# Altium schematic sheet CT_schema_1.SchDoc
size 554 x 508 mm
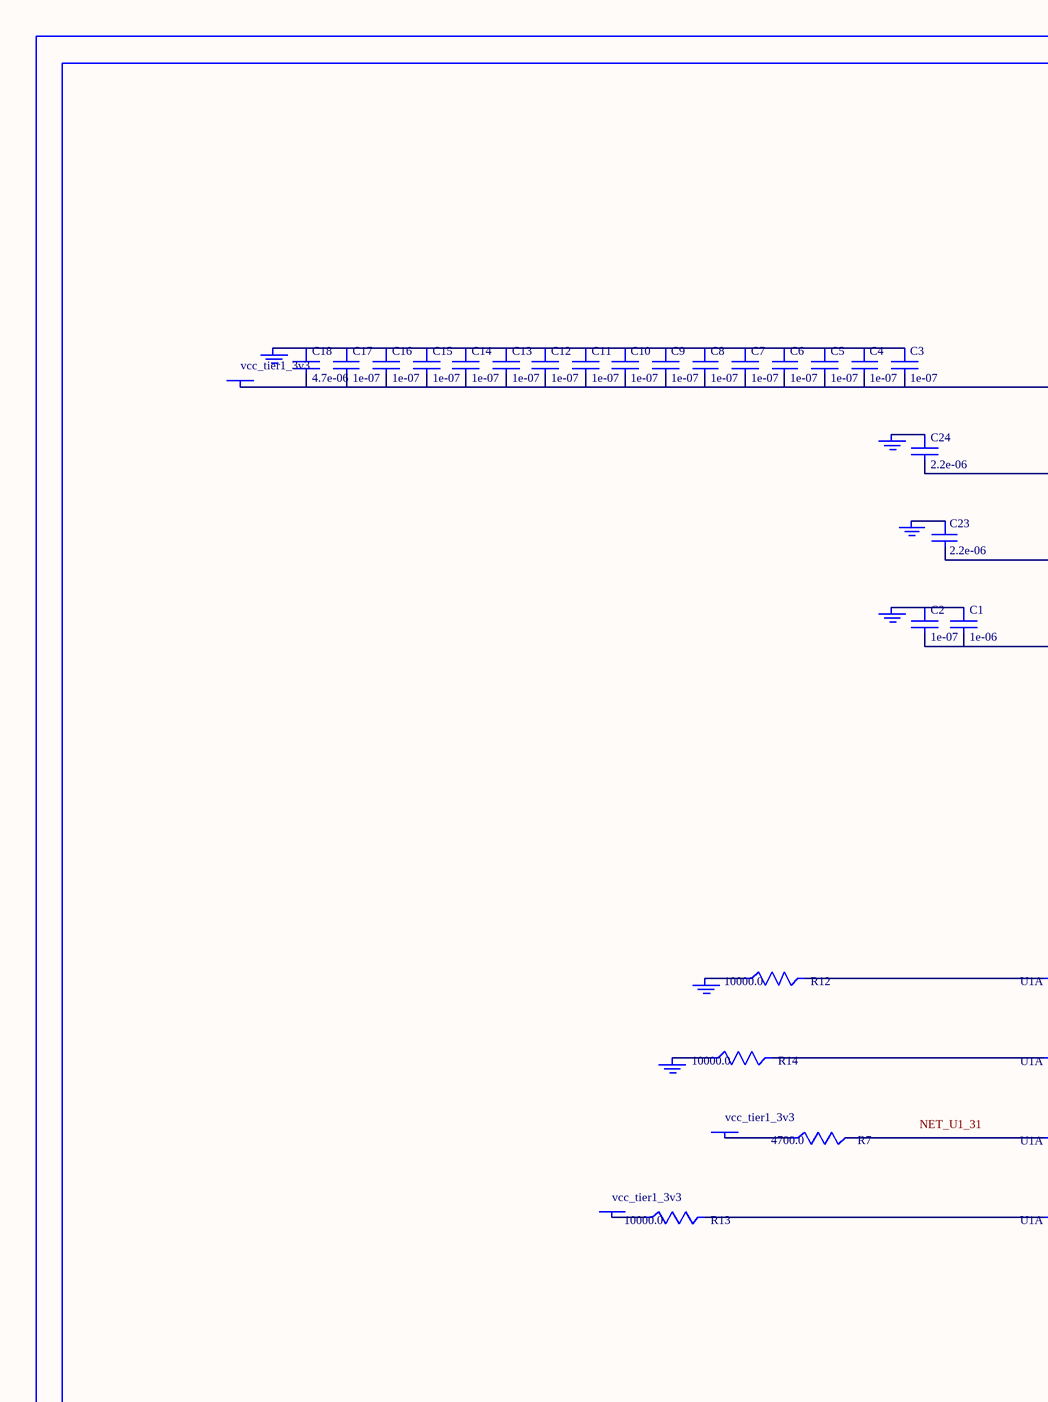
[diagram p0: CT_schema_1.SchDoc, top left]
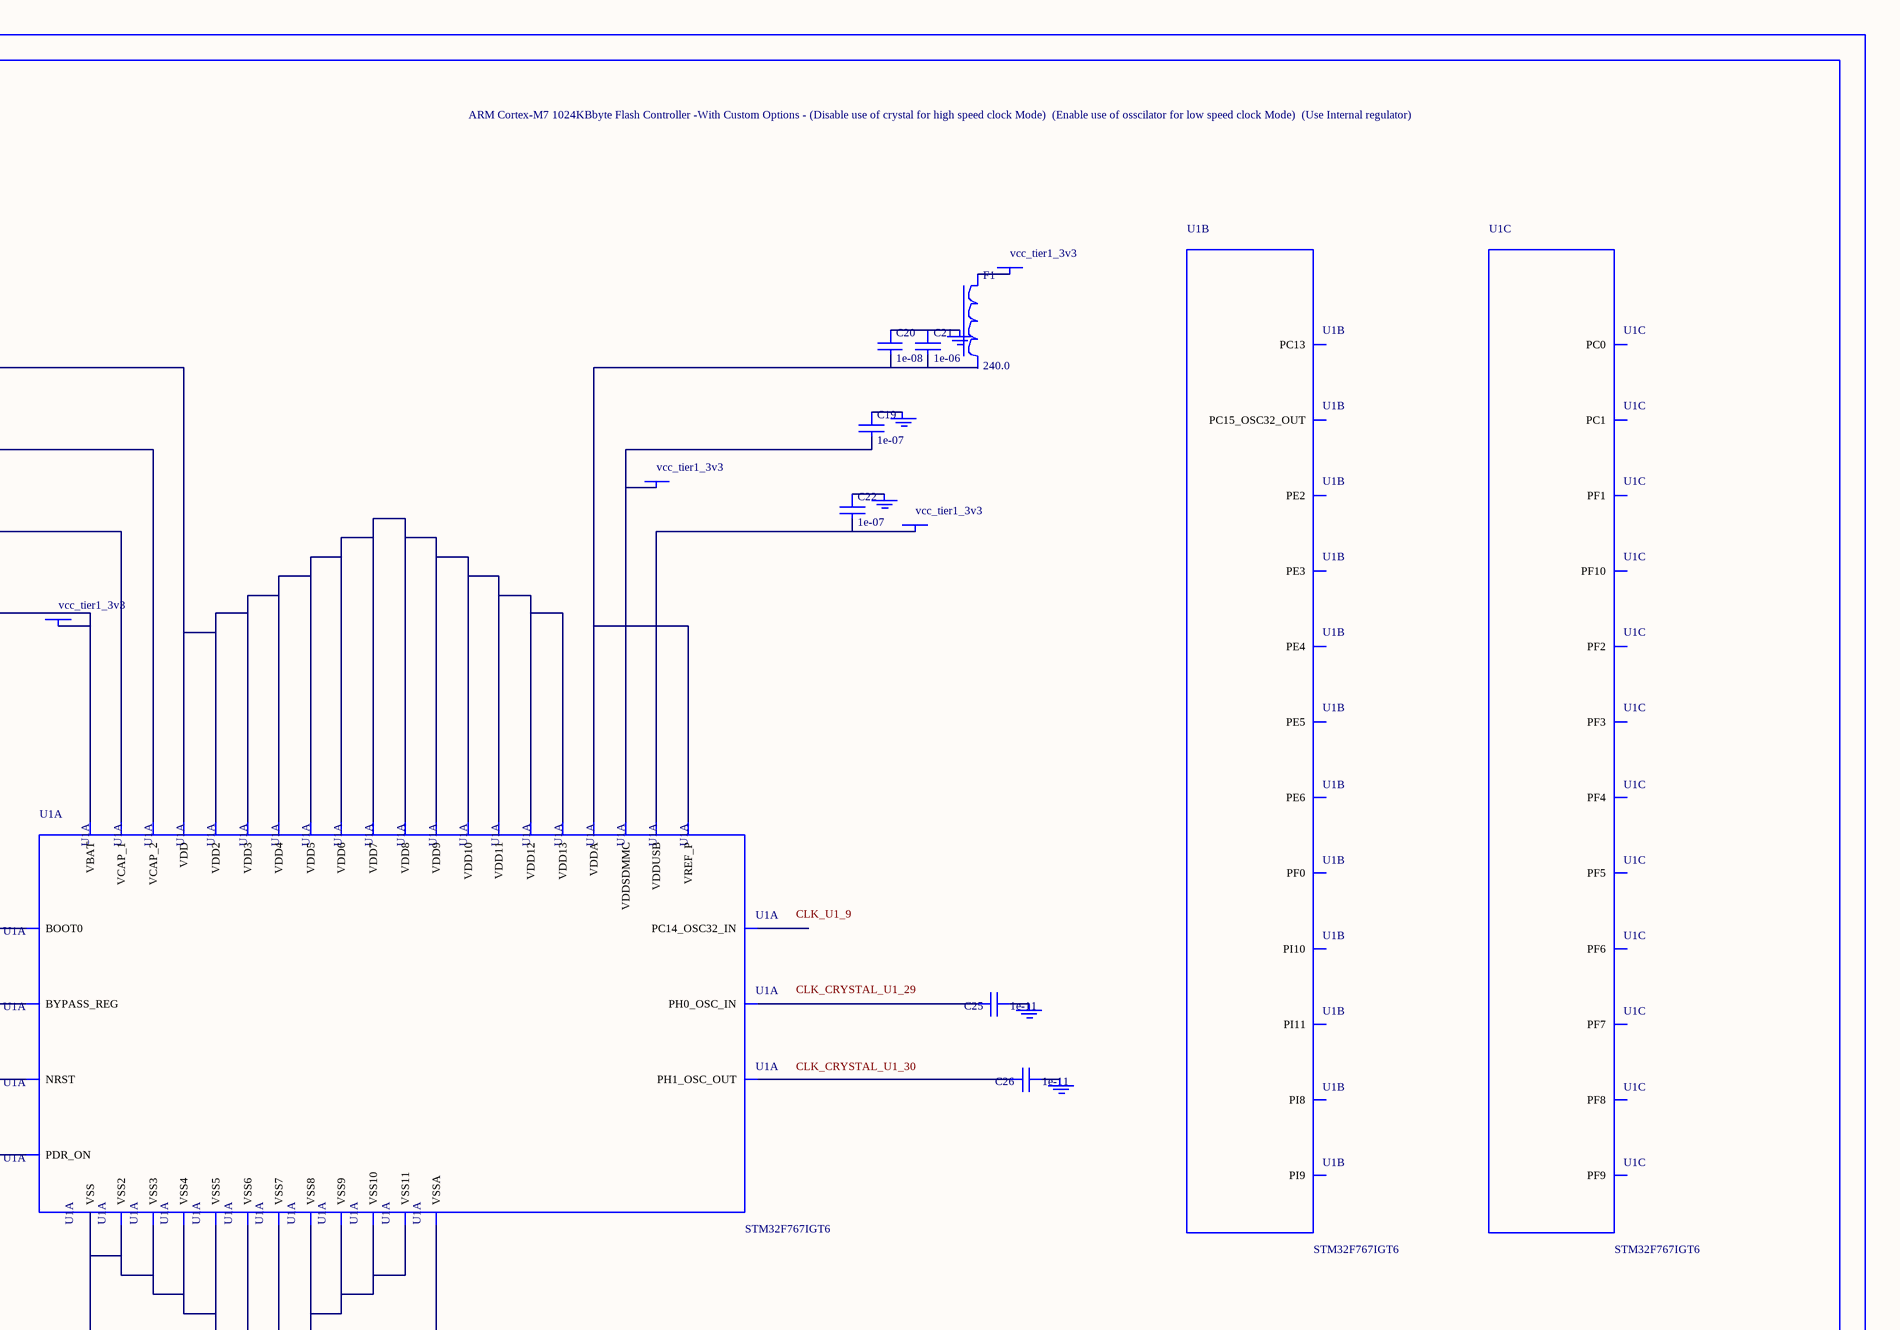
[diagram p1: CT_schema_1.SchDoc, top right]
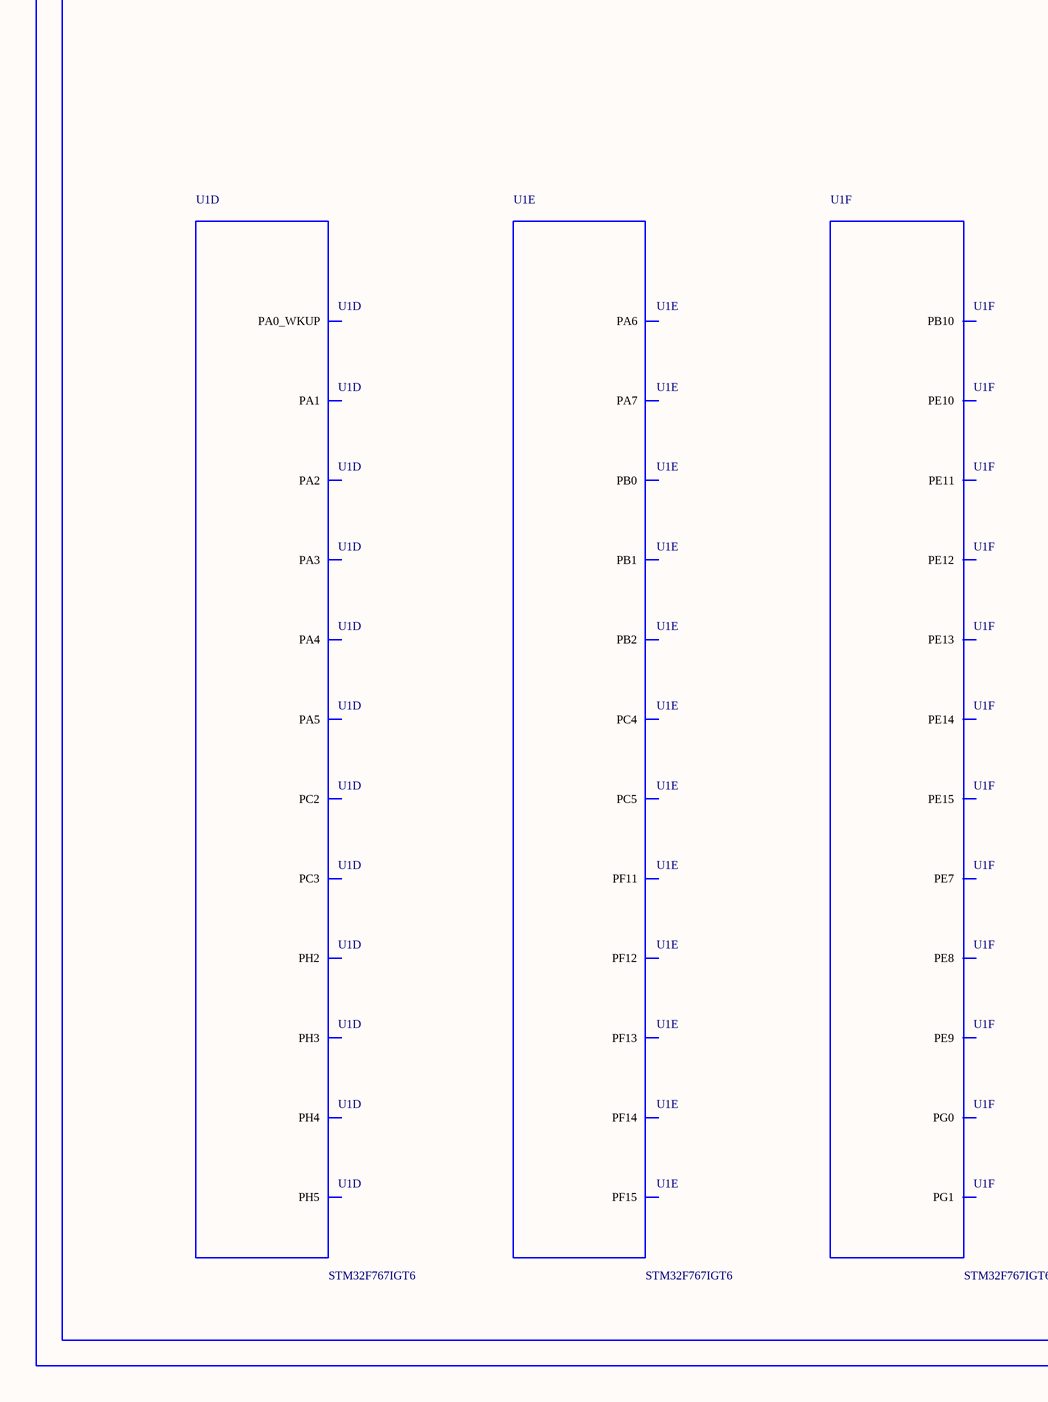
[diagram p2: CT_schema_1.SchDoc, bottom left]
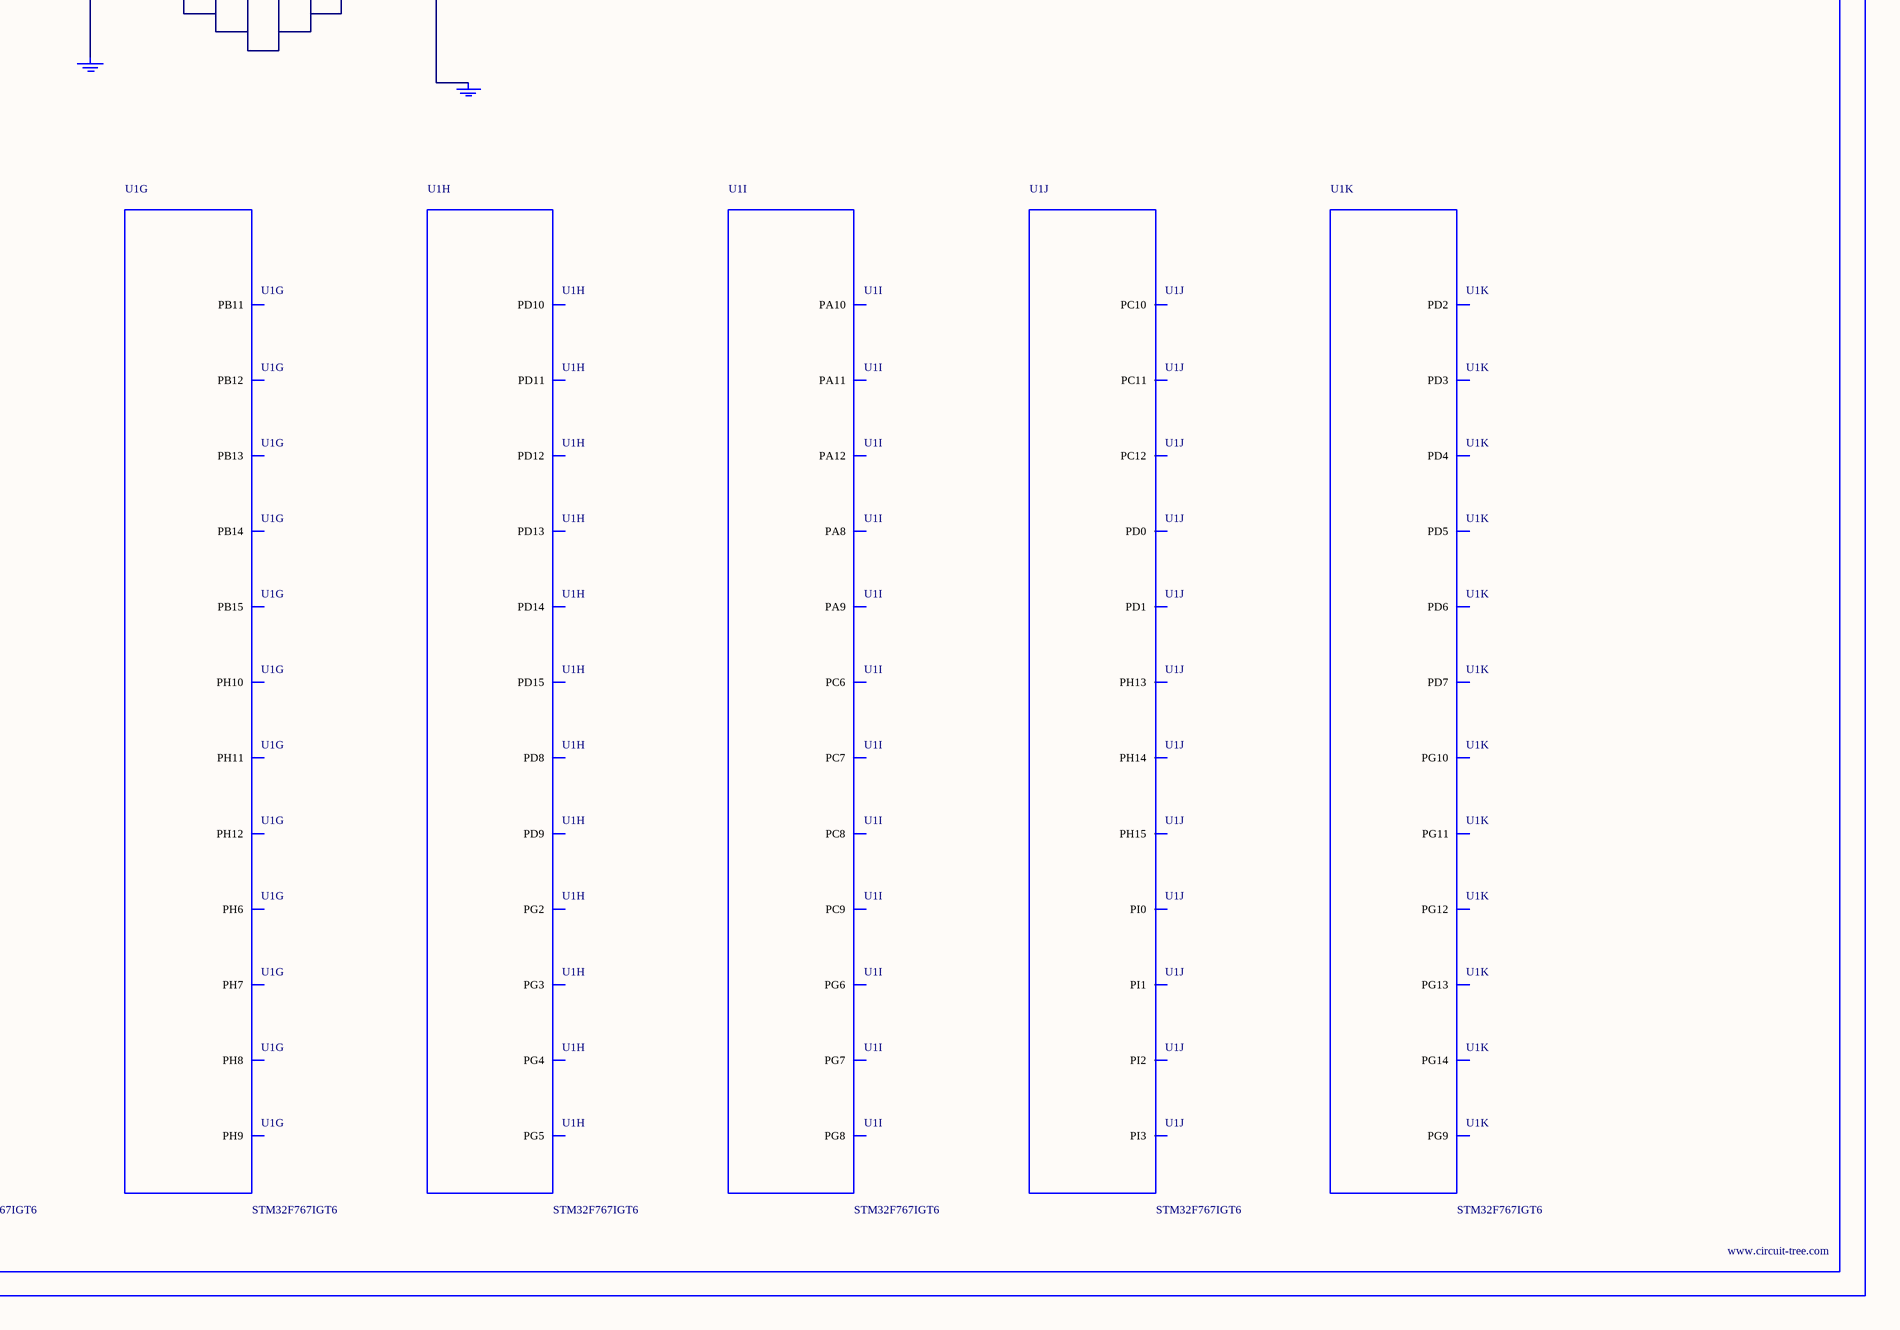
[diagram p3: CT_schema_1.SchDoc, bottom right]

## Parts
BORDER0  (no value)
C1  1e-06  [C0603]
C2  1e-07  [C0603]
C3  1e-07  [C0603]
C4  1e-07  [C0603]
C5  1e-07  [C0603]
C6  1e-07  [C0603]
C7  1e-07  [C0603]
C8  1e-07  [C0603]
C9  1e-07  [C0603]
C10  1e-07  [C0603]
C11  1e-07  [C0603]
C12  1e-07  [C0603]
C13  1e-07  [C0603]
C14  1e-07  [C0603]
C15  1e-07  [C0603]
C16  1e-07  [C0603]
C17  1e-07  [C0603]
C18  4.7e-06  [C0603]
C19  1e-07  [C0603]
C20  1e-08  [C0603]
C21  1e-06  [C0603]
C22  1e-07  [C0603]
C23  2.2e-06  [C0603]
C24  2.2e-06  [C0603]
C25  1e-11  [C0402]
C26  1e-11  [C0402]
F1  240.0  [L0603]
GND_INSTANCE_0_0  (no value)
GND_INSTANCE_0_1  (no value)
GND_INSTANCE_0_2  (no value)
GND_INSTANCE_0_3  (no value)
GND_INSTANCE_0_4  (no value)
GND_INSTANCE_0_5  (no value)
GND_INSTANCE_0_6  (no value)
GND_INSTANCE_0_7  (no value)
GND_INSTANCE_0_8  (no value)
GND_INSTANCE_0_9  (no value)
GND_INSTANCE_0_10  (no value)
GND_INSTANCE_0_11  (no value)
GND_INSTANCE_0_12  (no value)
POWER_INSTANCE_0_0  vcc_tier1_3v3
POWER_INSTANCE_0_1  vcc_tier1_3v3
POWER_INSTANCE_0_2  vcc_tier1_3v3
POWER_INSTANCE_0_3  vcc_tier1_3v3
POWER_INSTANCE_0_4  vcc_tier1_3v3
POWER_INSTANCE_0_5  vcc_tier1_3v3
POWER_INSTANCE_0_6  vcc_tier1_3v3
R7  4700.0  [R0603]
R12  10000.0  [R0603]
R13  10000.0  [R0603]
R14  10000.0  [R0603]
U1  STM32F767IGT6  [LQFP176]  (parts A,B,C,D,E,F,G,H,I,J,K of 13)

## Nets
NetC1_1: C1.1 C2.1 GND_INSTANCE_0_0.0(GND)
NetC1_2: C1.2 C2.2 POWER_INSTANCE_0_0.0(PWR) U1.6(VBAT)
NetC3_1: C3.1 C4.1 C5.1 C6.1 C7.1 C8.1 C9.1 C10.1 C11.1 C12.1 C13.1 C14.1 C15.1 C16.1 C17.1 C18.1 GND_INSTANCE_0_1.0(GND)
NetC3_2: C3.2 C4.2 C5.2 C6.2 C7.2 C8.2 C9.2 C10.2 C11.2 C12.2 C13.2 C14.2 C15.2 C16.2 C17.2 C18.2 POWER_INSTANCE_0_1.0(PWR) U1.15(VDD) U1.23(VDD2) U1.36(VDD3) U1.49(VDD4) U1.62(VDD5) U1.72(VDD6) U1.82(VDD7) U1.91(VDD8) U1.103(VDD9) U1.127(VDD10) U1.136(VDD11) U1.159(VDD12) U1.172(VDD13)
NetC19_1: C19.1 GND_INSTANCE_0_10.0(GND)
NetC19_2: C19.2 POWER_INSTANCE_0_4.0(PWR) U1.149(VDDSDMMC)
NetC20_1: C20.1 C21.1 GND_INSTANCE_0_5.0(GND)
NetC20_2: C20.2 C21.2 U1.38(VREF_P) U1.39(VDDA)
NetC22_1: C22.1 GND_INSTANCE_0_8.0(GND)
NetC22_2: C22.2 POWER_INSTANCE_0_3.0(PWR) U1.114(VDDUSB)
NetC23_1: C23.1 GND_INSTANCE_0_7.0(GND)
NetC23_2: C23.2 U1.81(VCAP_1)
NetC24_1: C24.1 GND_INSTANCE_0_9.0(GND)
NetC24_2: C24.2 U1.125(VCAP_2)
NetC25_1: C25.1 GND_INSTANCE_0_2.0(GND)
NetC25_2: C25.2 U1.29(PH0_OSC_IN)
NetC26_1: C26.1 GND_INSTANCE_0_3.0(GND)
NetC26_2: C26.2 U1.30(PH1_OSC_OUT)
NetF1_1: F1.1 POWER_INSTANCE_0_2.0(PWR)
NetGND_INSTANCE_0_4_0: GND_INSTANCE_0_4.0(GND) U1.37(VSSA)
NetGND_INSTANCE_0_6_0: GND_INSTANCE_0_6.0(GND) R14.1
NetGND_INSTANCE_0_11_0: GND_INSTANCE_0_11.0(GND) R12.1
NetGND_INSTANCE_0_12_0: GND_INSTANCE_0_12.0(GND) U1.14(VSS) U1.22(VSS2) U1.61(VSS3) U1.71(VSS4) U1.90(VSS5) U1.102(VSS6) U1.113(VSS7) U1.126(VSS8) U1.135(VSS9) U1.148(VSS10) U1.158(VSS11)
NetPOWER_INSTANCE_0_5_0: POWER_INSTANCE_0_5.0(PWR) R13.1
NetPOWER_INSTANCE_0_6_0: POWER_INSTANCE_0_6.0(PWR) R7.1
NetR7_2: R7.2 U1.31(NRST)
NetR12_2: R12.2 U1.166(BOOT0)
NetR13_2: R13.2 U1.171(PDR_ON)
NetR14_2: R14.2 U1.48(BYPASS_REG)

Not connected (* = marked no-connect by the designer): F1 2; U1 1(PE2) 2(PE3) 3(PE4) 4(PE5) 5(PE6) 7(PI8) 8(PC13) 9(PC14_OSC32_IN) 10(PC15_OSC32_OUT) 11(PI9) 12(PI10) 13(PI11) 16(PF0) 17(PF1) 18(PF2) 19(PF3) 20(PF4) 21(PF5) 24(PF6) 25(PF7) 26(PF8) 27(PF9) 28(PF10) 32(PC0) 33(PC1) 34(PC2) 35(PC3) 40(PA0_WKUP) 41(PA1) 42(PA2) 43(PH2) 44(PH3) 45(PH4) 46(PH5) 47(PA3) 50(PA4) 51(PA5) 52(PA6) 53(PA7) 54(PC4) 55(PC5) 56(PB0) 57(PB1) 58(PB2) 59(PF11) 60(PF12) 63(PF13) 64(PF14) 65(PF15) 66(PG0) 67(PG1) 68(PE7) 69(PE8) 70(PE9) 73(PE10) 74(PE11) 75(PE12) 76(PE13) 77(PE14) 78(PE15) 79(PB10) 80(PB11) 83(PH6) 84(PH7) 85(PH8) 86(PH9) 87(PH10) 88(PH11) 89(PH12) 92(PB12) 93(PB13) 94(PB14) 95(PB15) 96(PD8) 97(PD9) 98(PD10) 99(PD11) 100(PD12) 101(PD13) 104(PD14) 105(PD15) 106(PG2) 107(PG3) 108(PG4) 109(PG5) 110(PG6) 111(PG7) 112(PG8) 115(PC6) 116(PC7) 117(PC8) 118(PC9) 119(PA8) 120(PA9) 121(PA10) 122(PA11) 123(PA12) 128(PH13) 129(PH14) 130(PH15) 131(PI0) 132(PI1) 133(PI2) 134(PI3) 139(PC10) 140(PC11) 141(PC12) 142(PD0) 143(PD1) 144(PD2) 145(PD3) 146(PD4) 147(PD5) 150(PD6) 151(PD7) 152(PG9) 153(PG10) 154(PG11) 155(PG12) 156(PG13) 157(PG14)

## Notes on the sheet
- Labels drawn without touching a wire or pin: CLK_CRYSTAL_U1_29, CLK_CRYSTAL_U1_30, CLK_U1_9, NET_U1_31

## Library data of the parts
BORDER0 = BORDER_PAGE0
C1 C21 = C0603C105K3RACTU
C2-C17 C19 C22 = 06035C104K4Z2A
C18 = GRM188R6YA475KE15D
C20 = 06035C103K4Z2A
C23 C24 = C0603C225K8RACTU
C25 C26 = C0402C100K3GACTU
F1 = Z0603C241ASMST
GND_INSTANCE_0_0-GND_INSTANCE_0_12 = GND
POWER_INSTANCE_0_0-POWER_INSTANCE_0_6 = PWR
R7 = RC0603JR-074K7L
R12-R14 = RC0603JR-0710KL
